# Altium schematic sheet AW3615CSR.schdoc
size 127 x 101 mm
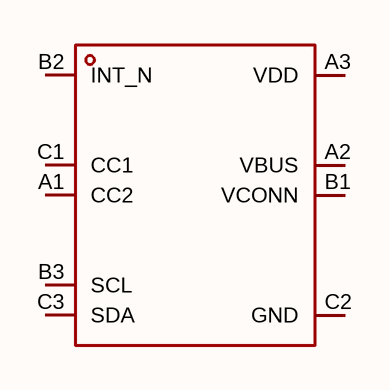
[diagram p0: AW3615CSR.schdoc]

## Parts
U?  aw3615csr  [WLCSP-9_L1.4-W1.4-R3-C3-P0.40-TL]  (value not drawn)

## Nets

Not connected (* = marked no-connect by the designer): U? A1(CC2) A2(VBUS) A3(VDD) B1(VCONN) B2(INT_N) B3(SCL) C1(CC1) C2(GND) C3(SDA)

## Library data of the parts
U? = aw3615csr: 功能类型:升压型;工作电压:2.8V~4.5V;输出电压:3.3V~5.5V;输出电流:1.5A;输出类型:可调;; Manufacturer: AWINIC(艾为); AddInBom: yes; ModelId: d95567b99d964bc7be5af2d073d6149a; ModelName: WLCSP-9_L1.4-W1.4-H0.6-R3-C3-P0.40-TL; ModelTransform: 55.118,55.118,0,0,0,0,0,0.002,0; Function: 升压型; Output Current: 1.5A; Frequency - Switching: 1.6MHz~2.4MHz; Synchronous Rectifier: 是; Number of Outputs: 1; Topology: 升压式; Quiescent Current: 80uA; Switch tube (built-in/external): 内置; Output Type: 可调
